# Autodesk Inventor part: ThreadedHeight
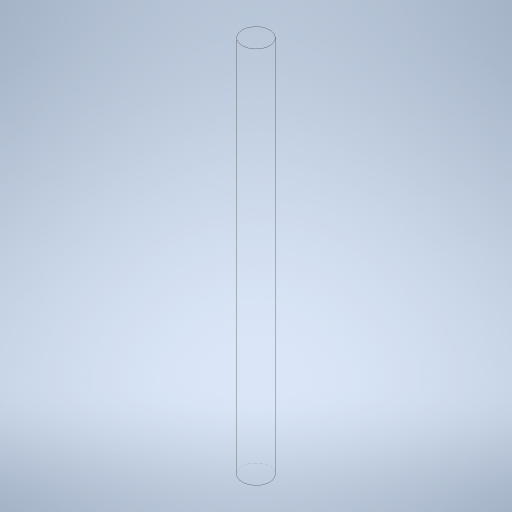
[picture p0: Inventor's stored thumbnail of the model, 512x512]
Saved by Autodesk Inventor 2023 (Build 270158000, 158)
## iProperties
Created: 2023-11
Part Number: ThreadedHeight
Material: Generic
Document SubType Name: Modeling
Designer: tornqvih
Density: 1 g/cm^3
Appearance: Default
Author: tornqvih
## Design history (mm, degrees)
sketch "Sketch1"
  geometry: C1 r 8 at (0, 0); 1 further point
  constraints: 1 centre point, 1 coincident
  dimensions: "d0" = 16 diameter of C1
extrude "Extrusion1" new body sketch "Sketch1" distance "d1" = 220; taper "d2" = 0 deg
thread "Thread1" dims "d3" = 200, "d4" = 0
body "Solid1"
